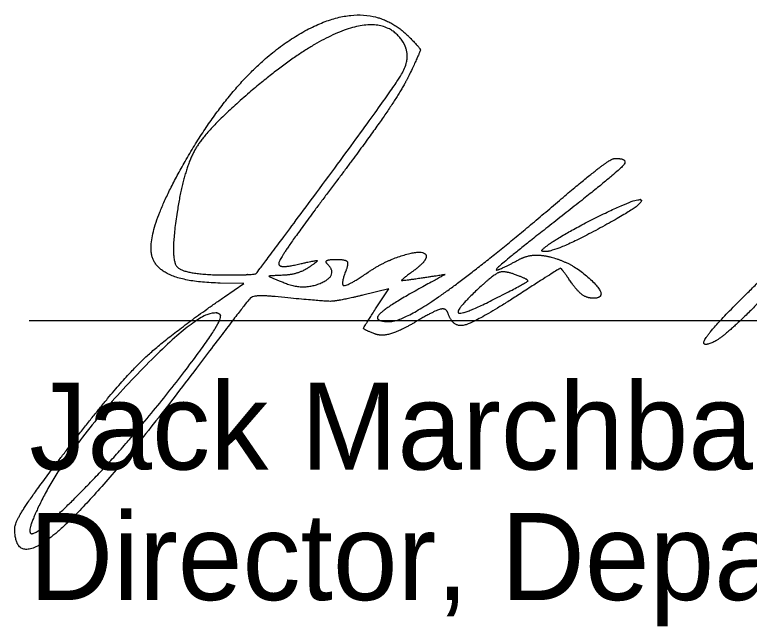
# Model space of a CAD drawing. Extents: x -8 to 42.1, y -22 to 0.
# Drawn here: x 24.504 to 25.687, y -15.007 to -14.023 of the extents above; entities that cross this region are included whole.
import ezdxf

# ---------------------------------------------------------------- set-up
doc = ezdxf.new("R2010")
doc.units = 0
doc.layers.add('SH_Data', color=7, linetype='Continuous')
doc.layers.add('SH_Text', color=7, linetype='Continuous')

msp = doc.modelspace()

# ---------------------------------------------------------------- linework, layer by layer
at = {"layer": 'SH_Data'}
msp.add_line((24.5279, -14.5152), (28.0279, -14.5152), dxfattribs=at)
at = {"layer": 'SH_Text'}
for p, q in [((24.9902, -14.3101), (24.9902, -14.3101)), ((25.3555, -14.4), (25.3555, -14.4)), ((25.3107, -14.4417), (25.3107, -14.4417))]:
    msp.add_line(p, q, dxfattribs=at)
for points in [[(24.8425, -14.4771), (24.8732, -14.4559), (24.8354, -14.4552)], [(25.0855, -14.4969), (25.1067, -14.4646), (25.0649, -14.4747)]]:
    msp.add_lwpolyline(points, dxfattribs=at)
for points in [[(24.7789, -14.2594), (24.8651, -14.109), (25.0732, -13.993), (25.1389, -14.0586)], [(25.1299, -14.0678), (25.104, -14.0258), (24.9779, -14.067), (24.8825, -14.1486)], [(25.1389, -14.0586), (25.1577, -14.0774), (25.1577, -14.0825), (25.1394, -14.1209)], [(24.9902, -14.3101), (25.1115, -14.1467), (25.144, -14.0905), (25.1299, -14.0678)], [(25.1394, -14.1209), (25.1284, -14.1439), (25.0767, -14.2194), (25.0245, -14.2888)], [(24.8825, -14.1486), (24.8159, -14.2056), (24.7771, -14.2697), (24.766, -14.341)], [(24.8354, -14.4552), (24.7375, -14.4535), (24.7141, -14.3724), (24.7789, -14.2594)], [(25.369, -14.3329), (25.4194, -14.29), (25.4649, -14.2549), (25.4701, -14.2547)], [(25.4701, -14.2547), (25.495, -14.2542), (25.4716, -14.2798), (25.3857, -14.3471)], [(25.0245, -14.2888), (24.9722, -14.3581), (24.9295, -14.4188), (24.9295, -14.4236)], [(24.844, -14.4421), (24.8907, -14.4421), (24.8953, -14.438), (24.9902, -14.3101)], [(25.3555, -14.4), (25.3759, -14.3821), (25.5079, -14.3164), (25.5131, -14.3215)], [(25.5131, -14.3215), (25.5193, -14.3277), (25.3767, -14.4046), (25.359, -14.4046)], [(25.1076, -14.5171), (25.1307, -14.5171), (25.2567, -14.4283), (25.369, -14.3329)], [(24.766, -14.341), (24.7545, -14.4143), (24.776, -14.4421), (24.844, -14.4421)], [(25.3857, -14.3471), (25.2925, -14.4201), (25.271, -14.4416), (25.315, -14.4181)], [(25.0736, -14.4377), (25.1025, -14.4179), (25.167, -14.4004), (25.167, -14.4123)], [(25.359, -14.4046), (25.3542, -14.4046), (25.3526, -14.4025), (25.3555, -14.4)], [(25.0086, -14.4253), (25.004, -14.4208), (25.0103, -14.4171), (25.0225, -14.4171)], [(25.0225, -14.4171), (25.037, -14.4171), (25.0422, -14.4235), (25.0375, -14.4358)], [(25.167, -14.4123), (25.167, -14.4168), (25.1572, -14.4277), (25.1453, -14.4364)], [(25.315, -14.4181), (25.3276, -14.4114), (25.3515, -14.4093), (25.3681, -14.4135)], [(25.3681, -14.4135), (25.4042, -14.4226), (25.4625, -14.4796), (25.4358, -14.4796)], [(24.9295, -14.4236), (24.9295, -14.4284), (24.9449, -14.4287), (24.9638, -14.4243)], [(24.9795, -14.429), (24.9692, -14.436), (24.9495, -14.4421), (24.9357, -14.4427)], [(24.9399, -14.4553), (24.9698, -14.4673), (25.026, -14.4427), (25.0086, -14.4253)], [(24.9638, -14.4243), (24.9894, -14.4184), (24.9934, -14.4196), (24.9795, -14.429)], [(25.617, -14.5539), (25.6067, -14.5537), (25.6563, -14.4975), (25.7273, -14.429)], [(25.0375, -14.4358), (25.0285, -14.4591), (25.0414, -14.4597), (25.0736, -14.4377)], [(25.1453, -14.4364), (25.1264, -14.4502), (25.1284, -14.4515), (25.161, -14.4466)], [(25.161, -14.4466), (25.1977, -14.441), (25.1976, -14.4413), (25.1522, -14.4664)], [(25.3107, -14.4417), (25.2935, -14.4353), (25.277, -14.4404), (25.2576, -14.4582)], [(25.4011, -14.4549), (25.3843, -14.4308), (25.3822, -14.4313), (25.3165, -14.4736)], [(24.9357, -14.4427), (24.9133, -14.4435), (24.9138, -14.4449), (24.9399, -14.4553)], [(25.2826, -14.478), (25.329, -14.4543), (25.3325, -14.4497), (25.3107, -14.4417)], [(25.2576, -14.4582), (25.2133, -14.4987), (25.2246, -14.5076), (25.2826, -14.478)], [(25.4358, -14.4796), (25.4262, -14.4796), (25.4106, -14.4685), (25.4011, -14.4549)], [(24.9237, -14.477), (24.8903, -14.4737), (24.8786, -14.4842), (24.8019, -14.5858)], [(25.0649, -14.4747), (25.0246, -14.4844), (25.0023, -14.4848), (24.9237, -14.477)], [(25.1522, -14.4664), (25.1011, -14.4946), (25.0814, -14.5171), (25.1076, -14.5171)], [(25.3165, -14.4736), (25.2476, -14.518), (25.2101, -14.5277), (25.202, -14.5034)], [(24.5916, -14.7193), (24.6692, -14.6188), (24.7493, -14.5415), (24.8425, -14.4771)], [(25.7045, -14.4842), (25.6667, -14.5227), (25.6273, -14.5541), (25.617, -14.5539)], [(25.0843, -14.537), (25.0661, -14.53), (25.0662, -14.5264), (25.0855, -14.4969)], [(25.202, -14.5034), (25.1991, -14.4948), (25.1799, -14.5), (25.1508, -14.5172)], [(24.8354, -14.5063), (24.8145, -14.4854), (24.596, -14.7111), (24.5497, -14.8014)], [(24.6198, -14.7827), (24.6874, -14.7136), (24.8431, -14.514), (24.8354, -14.5063)], [(25.1508, -14.5172), (25.1252, -14.5323), (25.0953, -14.5412), (25.0843, -14.537)], [(24.8019, -14.5858), (24.6496, -14.7879), (24.5045, -14.9165), (24.5045, -14.8495)], [(24.5045, -14.8495), (24.5045, -14.8399), (24.5437, -14.7813), (24.5916, -14.7193)], [(24.5497, -14.8014), (24.5184, -14.8624), (24.55, -14.8539), (24.6198, -14.7827)]]:
    msp.add_open_spline(points, degree=2, dxfattribs=at)

# ---------------------------------------------------------------- texts
for s, p in [('Jack Marchbanks, PhD', (24.5279, -14.7552)), ('Director, Department of Transportation', (24.5279, -14.9652))]:
    msp.add_text(s, height=0.14, dxfattribs=at).set_placement(p)

doc.saveas('drawing.dxf')
